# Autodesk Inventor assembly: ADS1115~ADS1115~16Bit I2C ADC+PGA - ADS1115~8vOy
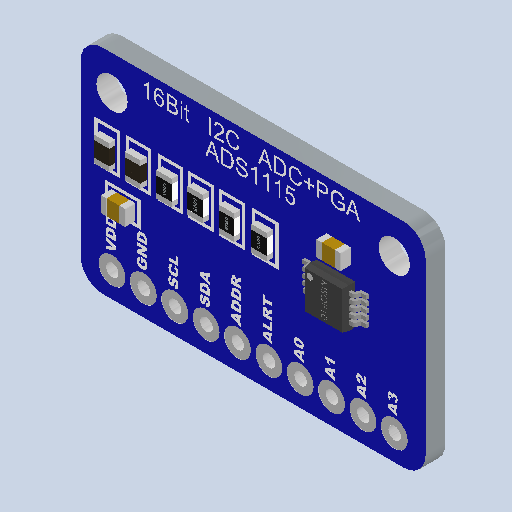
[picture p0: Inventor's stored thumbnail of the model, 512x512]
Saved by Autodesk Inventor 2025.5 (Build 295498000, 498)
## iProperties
Created: 2026-10
Part Number: ADS1115~ADS1115~16Bit I2C ADC+PGA - ADS1115~8vOy
Description: 16Bit I2C ADC+PGA - ADS1115
Document SubType Name: Assembly
Designer: Luis M
Author: Luis M
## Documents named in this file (6)
- C:\Users\Luis M\Downloads\3D_PCB1_2026-10-28\ADS1115~ADS1115~16Bit I2C ADC+PGA - ADS1115~8vOy.iam
- C:\Users\Luis M\Downloads\3D_PCB1_2026-10-28\ADS1115~16Bit I2C ADC+PGA - ADS1115~ZaZa.ipt
- C:\Users\Luis M\Downloads\3D_PCB1_2026-10-28\ADS1115~16Bit I2C ADC+PGA - ADS1115~ZaZa_1.ipt
- C:\Users\Luis M\Downloads\3D_PCB1_2026-10-28\ADS1115~16Bit I2C ADC+PGA - ADS1115~ZaZa_2.ipt
- C:\Users\Luis M\Downloads\3D_PCB1_2026-10-28\ADS1115~16Bit I2C ADC+PGA - ADS1115~ZaZa_3.ipt
- C:\Users\Luis M\Downloads\3D_PCB1_2026-10-28\ADS1115~16Bit I2C ADC+PGA - ADS1115~ZaZa_4.ipt
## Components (10 placed, 5 different names)
1. ADS1115
2. 0805 Capacitor
3. 0805 Capacitor:1
4. 0805 Inductor
5. 0805 Inductor:1
6. 0805 Resistor
7. 0805 Resistor:1
8. 0805 Resistor:2
9. 0805 Resistor:3
10. MSOP10
